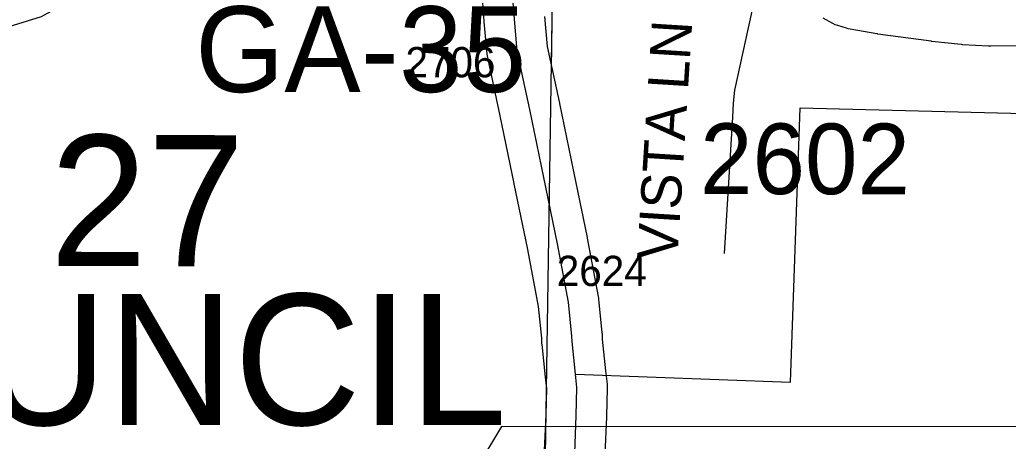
# Model space of a CAD drawing. Extents: x -132.8 to -73.3, y -60 to -26.
# Drawn here: x -118.411 to -117.43, y -48.87 to -48.452 of the extents above; entities that cross this region are included whole.
import ezdxf

# ---------------------------------------------------------------- set-up
doc = ezdxf.new("R2010")
doc.units = 0
for name, color, linetype in [('tdCoCorpBndry', 7, 'Continuous'), ('tdCoCorpTxt', 7, 'Continuous'), ('tdCoDirctArrow', 7, 'Continuous'), ('tdCoHydroRiver', 7, 'Continuous'), ('tdCoSecRdNmbr', 7, 'Continuous'), ('tdCoSecRdTxt', 7, 'Continuous'), ('tdCoSecRteBand', 7, 'Continuous'), ('tdCoSecRteCL', 7, 'Continuous'), ('tdCoSectLine', 7, 'Continuous'), ('tdCoSectLinePart', 7, 'Continuous'), ('tdCoSectNmbr', 7, 'Continuous'), ('tdCoStrucSecCoName', 7, 'Continuous'), ('tdCoSurfConc', 7, 'Continuous'), ('tdCoSurfConcUnbanded', 7, 'Continuous')]:
    doc.layers.add(name, color=color, linetype=linetype)

msp = doc.modelspace()

# ---------------------------------------------------------------- linework, layer by layer
at = {"layer": 'tdCoCorpBndry'}
msp.add_lwpolyline([(-117.86041, -48.88169), (-117.85892, -48.84496), (-117.85818, -48.81691), (-117.85958, -48.80367), (-117.64623, -48.81178), (-117.63685, -48.53952), (-117.38876, -48.54588)], dxfattribs=at)
at = {"layer": 'tdCoDirctArrow'}
msp.add_lwpolyline([(-117.18194, -48.85609), (-117.93302, -48.85564), (-118.00947, -48.98238)], dxfattribs=at)
at = {"layer": 'tdCoHydroRiver'}
msp.add_lwpolyline([(-117.98585, -48.0942), (-118.01487, -48.11708), (-118.04527, -48.13204), (-118.06628, -48.1504), (-118.0979, -48.21108), (-118.12057, -48.23255), (-118.16562, -48.26447), (-118.21814, -48.2804), (-118.31229, -48.37725), (-118.36757, -48.43729), (-118.38999, -48.4493), (-118.4457, -48.46673), (-118.47166, -48.49285), (-118.50738, -48.52975), (-118.53695, -48.57313), (-118.57957, -48.63193), (-118.60208, -48.64709), (-118.63379, -48.65254), (-118.65762, -48.65821), (-118.69777, -48.68395), (-118.7577, -48.7407), (-118.84316, -48.80781), (-118.87734, -48.84633), (-118.90841, -48.88651)], dxfattribs=at)
at = {"layer": 'tdCoSecRteBand'}
for points in [[(-117.89034, -48.87952), (-117.88891, -48.84396), (-117.88822, -48.81809), (-117.88941, -48.80682), (-117.89284, -48.77442), (-117.89293, -48.77349), (-117.89297, -48.77255), (-117.89316, -48.76817), (-117.89643, -48.7366), (-117.9069, -48.68024), (-117.92055, -48.61489), (-117.92057, -48.61482), (-117.92058, -48.61474), (-117.93428, -48.54745), (-117.94672, -48.48986), (-117.9471, -48.48809), (-117.94727, -48.48629), (-117.95023, -48.45429), (-117.95025, -48.454), (-117.95027, -48.45371), (-117.95267, -48.42093)], [(-117.89045, -48.44905), (-117.88769, -48.47896), (-117.87559, -48.53496), (-117.87555, -48.53513), (-117.87552, -48.53531), (-117.8618, -48.6027), (-117.8481, -48.6683), (-117.84803, -48.66862), (-117.84797, -48.66895), (-117.83721, -48.72683), (-117.83699, -48.72802), (-117.83687, -48.72923), (-117.83339, -48.7629), (-117.83329, -48.7638), (-117.83325, -48.76471), (-117.83307, -48.76906), (-117.82975, -48.80051), (-117.82835, -48.81376), (-117.82814, -48.81572), (-117.82819, -48.8177), (-117.82893, -48.84575), (-117.82894, -48.84596), (-117.82895, -48.84617), (-117.83043, -48.8829)], [(-117.36188, -48.47772), (-117.44771, -48.4786), (-117.44875, -48.47861), (-117.44979, -48.47855), (-117.47572, -48.47701), (-117.47643, -48.47697), (-117.47713, -48.47689), (-117.50593, -48.47381), (-117.50638, -48.47377), (-117.50682, -48.4737), (-117.55957, -48.46645), (-117.56012, -48.46638), (-117.56066, -48.46628), (-117.58703, -48.46167), (-117.58899, -48.46132), (-117.59089, -48.46072), (-117.59924, -48.45809), (-117.6019, -48.45725), (-117.60436, -48.45593), (-117.61381, -48.45088)]]:
    msp.add_lwpolyline(points, dxfattribs=at)
at = {"layer": 'tdCoSecRteCL'}
for points in [[(-117.86041, -48.88169), (-117.85892, -48.84496), (-117.85818, -48.81691), (-117.85958, -48.80367), (-117.863, -48.77127), (-117.86323, -48.76599), (-117.86671, -48.73231), (-117.87746, -48.67443), (-117.89118, -48.60876), (-117.90492, -48.54129), (-117.9174, -48.48353), (-117.92035, -48.45152), (-117.92275, -48.41874), (-117.92485, -48.37326), (-117.92387, -48.34527), (-117.92149, -48.32287), (-117.91939, -48.3044), (-117.91435, -48.27067), (-117.90623, -48.24072), (-117.89812, -48.21763), (-117.88958, -48.19636), (-117.87856, -48.17017)], [(-117.71184, -48.684), (-117.70345, -48.54886), (-117.70296, -48.53505), (-117.70148, -48.52222), (-117.68817, -48.46032), (-117.67879, -48.41816), (-117.67608, -48.40706), (-117.67337, -48.40065), (-117.66967, -48.39621), (-117.664, -48.39226), (-117.66019, -48.39123), (-117.65658, -48.39092), (-117.65149, -48.39114), (-117.64775, -48.39109), (-117.64454, -48.39038), (-117.64025, -48.38851), (-117.63577, -48.38525)]]:
    msp.add_lwpolyline(points, dxfattribs=at)
at = {"layer": 'tdCoSectLine'}
msp.add_lwpolyline([(-117.89784, -49.42438), (-117.88235, -48.43017)], dxfattribs=at)
at = {"layer": 'tdCoSectLinePart'}
msp.add_lwpolyline([(-117.88346, -48.50106), (-117.88235, -48.43017)], dxfattribs=at)
at = {"layer": 'tdCoSurfConc'}
msp.add_lwpolyline([(-117.86041, -48.88169), (-117.85892, -48.84496), (-117.85818, -48.81691), (-117.85958, -48.80367), (-117.863, -48.77127), (-117.86323, -48.76599), (-117.86671, -48.73231), (-117.87746, -48.67443), (-117.89118, -48.60876), (-117.90492, -48.54129), (-117.9174, -48.48353), (-117.92035, -48.45152)], dxfattribs=at)
at = {"layer": 'tdCoSurfConcUnbanded'}
msp.add_lwpolyline([(-117.71184, -48.684), (-117.70345, -48.54886), (-117.70296, -48.53505), (-117.70148, -48.52222), (-117.68817, -48.46032), (-117.67879, -48.41816), (-117.67608, -48.40706), (-117.67337, -48.40065), (-117.66967, -48.39621), (-117.664, -48.39226), (-117.66019, -48.39123), (-117.65658, -48.39092), (-117.65149, -48.39114), (-117.64775, -48.39109), (-117.64454, -48.39038), (-117.64025, -48.38851), (-117.63577, -48.38525)], dxfattribs=at)

# ---------------------------------------------------------------- texts
at = {"layer": 'tdCoCorpTxt'}
msp.add_text('COUNCIL', height=0.13, dxfattribs=at).set_placement((-118.71023, -48.85415))
at = {"layer": 'tdCoSecRdNmbr'}
for s, height, rotation, p in [('2706', 0.03, 359.91146, (-118.02839, -48.50929)), ('2602', 0.07, 359.91211, (-117.73609, -48.62503)), ('2624', 0.03, 359.91146, (-117.87825, -48.71626))]:
    msp.add_text(s, height=height, rotation=rotation, dxfattribs=at).set_placement(p)
at = {"layer": 'tdCoSecRdTxt'}
msp.add_text('VISTA LN', height=0.04, rotation=86.39609, dxfattribs=at).set_placement((-117.75873, -48.69157))
at = {"layer": 'tdCoSectNmbr'}
msp.add_text('27', height=0.13, rotation=359.91151, dxfattribs=at).set_placement((-118.38138, -48.69649))
at = {"layer": 'tdCoStrucSecCoName'}
msp.add_text('GA-35', height=0.085, dxfattribs=at).set_placement((-118.23695, -48.52397))

doc.saveas('drawing.dxf')
